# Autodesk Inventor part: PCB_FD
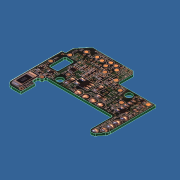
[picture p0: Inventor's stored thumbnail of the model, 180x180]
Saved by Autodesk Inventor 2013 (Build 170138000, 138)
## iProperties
Created: 2011-10
Part Number: PCB_FD
Document SubType Name: Modeling
Designer: Laur
Density: 1.38 g/cm^3
Material: Phénolique
Mass: 0.575758 g
Surface Area: 11.4869 cm^2
Volume: 0.417216 cm^3
Author: Laur
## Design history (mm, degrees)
sketch "Esquisse1"
  geometry: L1 (0.2, 0.766)-(0.2, 5.566); L2 (0.2, 5.566)-(-0.8, 6.566); L3 (-0.8, 6.566)-(-14.57, 6.566); L4 (-14.95, 6.392)-(-17.68, 3.207); L5 (-17.8, 2.881)-(-17.8, 0.766); L6 (-18.3, 0.266)-(-19, 0.266); L7 (-19, 0.266)-(-19, -16.934); L8 (-17, -18.934)-(-13.9, -18.934); L9 (-13.9, -18.934)-(-13.9, -14.034); L10 (-13.9, -14.034)-(-14.65, -14.034); L11 (-15.15, -13.534)-(-15.15, -12.234); L12 (-14.65, -11.734)-(-14.4, -11.734); L13 (-13.9, -11.234)-(-13.9, -10.934); L14 (-13.4, -10.434)-(8.7, -10.434); L15 (9.2, -10.934)-(9.2, -17.684); L16 (13.3, -15.43)-(13.3, 0.266); L17 (13.3, 0.266)-(0.7, 0.266); L18 (13.6, -18.934)-(3.914, -18.934); L19 (11.424, -18.467)-(12.859, -16.683); L20 (-27.6, 12.519)-(22.168, 12.519); L21 (22.168, 12.519)-(22.168, -24.807); L22 (22.168, -24.807)-(-27.6, -24.807); L23 (-27.6, -24.807)-(-27.6, 12.519); L24 (0, -32.272)-(0, 19.984) reference; L25 (-37.554, 0)-(32.121, 0) reference; A1 r 2 centre (-17, -16.934) between (-19, -16.934) and (-17, -18.934); A2 r 1.25 centre (10.45, -17.684) between (9.2, -17.684) and (11.424, -18.467); A3 r 2 centre (11.3, -15.43) between (12.859, -16.683) and (13.3, -15.43); A4 r 0.5 centre (0.7, 0.766) between (0.2, 0.766) and (0.7, 0.266); A5 r 0.5 centre (-18.3, 0.766) between (-18.3, 0.266) and (-17.8, 0.766); A6 r 0.5 centre (-14.65, -12.234) between (-14.65, -11.734) and (-15.15, -12.234); A7 r 0.5 centre (-14.65, -13.534) between (-15.15, -13.534) and (-14.65, -14.034); A8 r 0.5 centre (-14.4, -11.234) between (-14.4, -11.734) and (-13.9, -11.234); A9 r 0.5 centre (-13.4, -10.934) between (-13.4, -10.434) and (-13.9, -10.934); A10 r 0.5 centre (8.7, -10.934) between (9.2, -10.934) and (8.7, -10.434); A11 r 0.5 centre (-17.3, 2.881) between (-17.68, 3.207) and (-17.8, 2.881); A12 r 0.5 centre (-14.57, 6.066) between (-14.57, 6.566) and (-14.95, 6.392); 11 further points; 1 other entity
  constraints: 38 end point, 25 tangent, 24 point on circle, 20 point on line, 14 parallel, 12 centre point, 7 equal radius, 2 collinear, 2 vertical, 1 perpendicular, 2 other
  dimensions: "d0" = 1 distance from line of L3 L1.end; "d1" = 1 horizontal distance of L2.end L1.end (= d0); "d2" = 6.3 distance between parallel lines of L17 L3; "d3" = 3 horizontal distance of point (-17.8, 3.066) point (-14.8, 6.566); "d4" = 3.5 vertical distance of point (-17.8, 3.066) point (-14.8, 6.566); "d6" = 1.2 distance between parallel lines of L7 L5; "d7" = 2.8 distance from line of point (-17.8, 3.066) L6; "d8" = 19.2 distance between parallel lines of L8 L6; "d9" = 4.9 distance between parallel lines of L8 L10; "d10" = 5.1 distance between parallel lines of L7 L9; "d11" = 3.85 distance between parallel lines of L11 L7; "d12" = 2.3 distance between parallel lines of L10 L12; "d13" = 8.5 distance between parallel lines of L14 L8; "d14" = 23.1 distance between parallel lines of L15 L13; "d15" = 4.1 distance between parallel lines of L16 L15; "d17" = 32.3 distance between parallel lines of L16 L7 (derived); "d253" = 2 radius of A1; "d254" = 2.5 diameter of A2; "d256" = 2.8 distance from line of point (13.3, -16.134) L18; "d257" = 2 radius of A3; "d258" = 0.5 radius of A4; "d259" = 0.5 radius of A5; "d457" = 27.6 distance between parallel lines of L24 L23; "d460" = 12.51888 distance between parallel lines of L20 L25; "d461" = 13.1 distance between parallel lines of L1 L16; "d472" = 13.3 distance between parallel lines of L24 L16
  node "Image4"
extrude "contour" new body sketch "Esquisse1" distance "d18" = 0.8; taper "d19" = 0 deg
feature "recto PCB"
sketch "Esquisse3"
  geometry: L1 (-16.239, -0.883)-(-14.189, -0.883); L2 (-13.689, -1.383)-(-13.689, -6.033); L3 (-14.189, -6.533)-(-16.239, -6.533); L4 (-16.739, -6.033)-(-16.739, -1.383); C1 r 1.075 at (-10.769, -8.617); C2 r 1.075 at (5.731, -1.417); A1 r 0.5 centre (-16.239, -1.383) between (-16.239, -0.883) and (-16.739, -1.383); A2 r 0.5 centre (-14.189, -1.383) between (-13.689, -1.383) and (-14.189, -0.883); A3 r 0.5 centre (-16.239, -6.033) between (-16.739, -6.033) and (-16.239, -6.533); A4 r 0.5 centre (-14.189, -6.033) between (-14.189, -6.533) and (-13.689, -6.033)
  constraints: 8 end point, 8 point on circle, 8 tangent, 6 centre point, 3 equal radius, 2 parallel, 1 horizontal, 1 perpendicular
  dimensions: "d473" = 0.5 radius of A1; "d474" = 5.65 distance between parallel lines of L3 L1; "d475" = 3.05 distance between parallel lines of L2 L4; "d476" = 2.15 diameter of C1; "d477" = 2.15 diameter of C2; "d581" = 18.0025 distance of C2.centre C1.centre; "d582" = 7.2 vertical distance of C2.centre C1.centre
extrude "passages" cut sketch "Esquisse3" stored distance "d478" = 0.8; taper "d479" = 0 deg
sketch "Esquisse4"
  geometry: L1 (-0.7, 0.266)-(-13.3, 0.266) reference; L2 (-13.3, 0.266)-(-13.3, -15.43) reference; L3 (19, -16.934)-(19, 0.266) reference; L4 (23.726, -21.606)-(-17.909, -22.26); L5 (-17.909, -22.26)-(-18.4, 8.966); L6 (-18.4, 8.966)-(23.235, 9.62); L7 (23.235, 9.62)-(23.726, -21.606); 1 other entity
  constraints: 2 other
  dimensions: "d575" = 0.9 deg angle of L7 L3; "d577" = 8.7 distance from line of L5.end L1; "d578" = 5.1 distance from line of L5.end L2
feature "verso PCB" sketch "Esquisse4"
node "Solide1"
node "Corps solides"
node "Corps surfaciques"
node "Image6"
